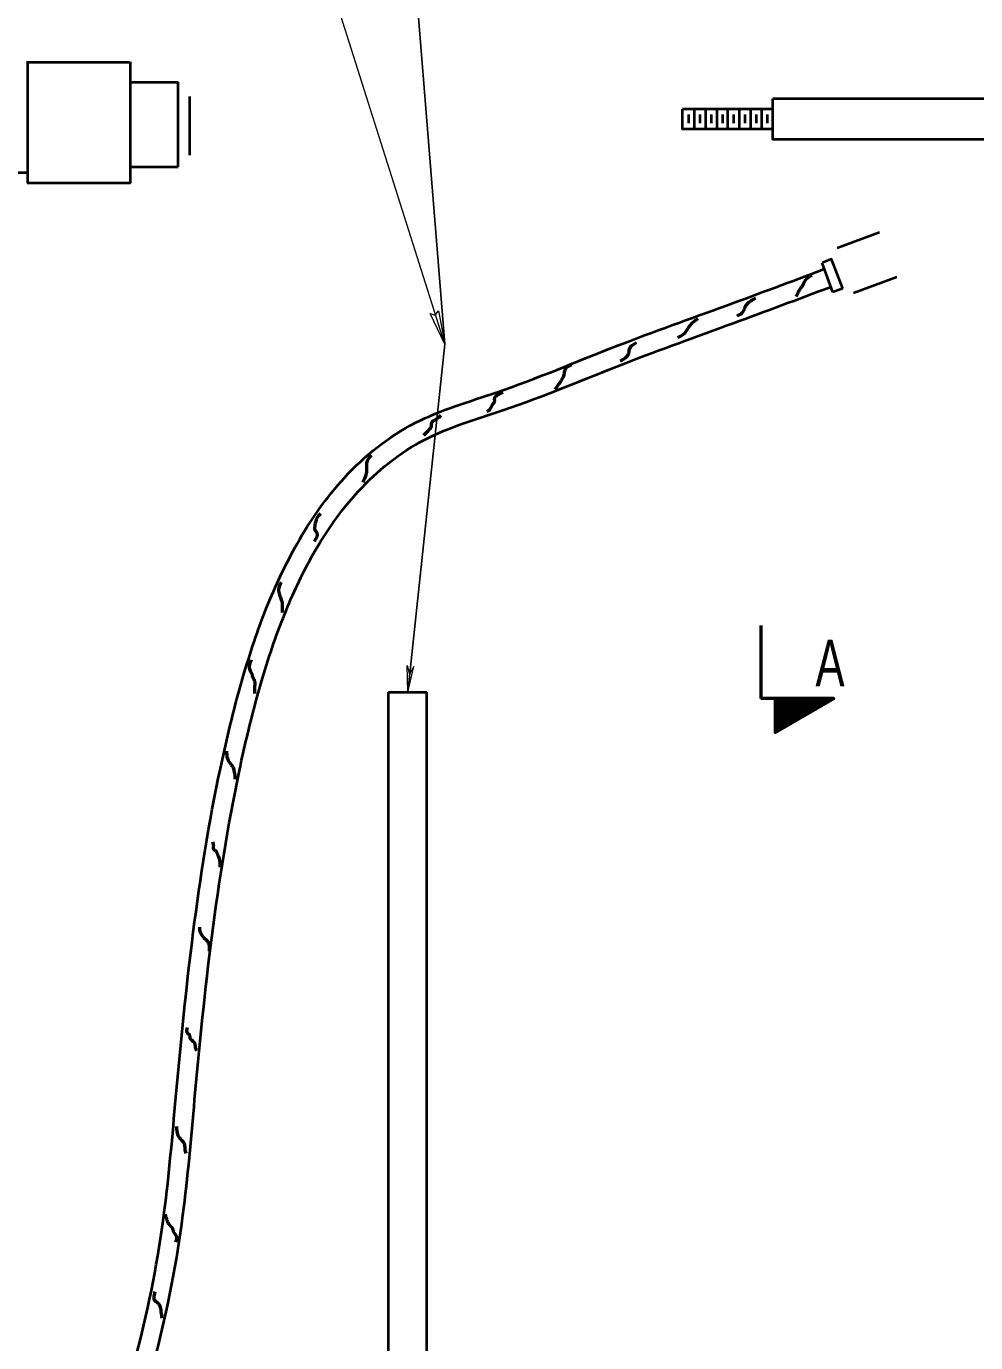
# Model space of a CAD drawing. Extents: x 312583 to 312854, y 144419 to 144597.
# Drawn here: x 312750.38 to 312765.92, y 144447.26 to 144468.81 of the extents above; entities that cross this region are included whole.
import ezdxf
from ezdxf.enums import TextEntityAlignment as Align

# ---------------------------------------------------------------- set-up
doc = ezdxf.new("R2010")
doc.units = 0
doc.header["$LTSCALE"] = 0.3
doc.layers.add('1', color=7, linetype='Continuous', lineweight=13)
doc.layers.add('2', color=7, linetype='Continuous', lineweight=13)

msp = doc.modelspace()

# ---------------------------------------------------------------- linework, layer by layer
at = {"layer": '1', "lineweight": 40}
for p, q in [((312752.069, 144468.2244), (312750.3824, 144468.2244)), ((312750.4054, 144466.2464), (312750.4054, 144468.2168)), ((312752.0844, 144466.2464), (312752.0844, 144468.2321)), ((312752.0844, 144467.9024), (312752.8664, 144467.9024)), ((312752.8664, 144466.5148), (312752.8664, 144467.9024)), ((312753.058, 144466.7064), (312753.058, 144467.6648)), ((312767.0037, 144467.6264), (312762.603, 144467.6264)), ((312762.603, 144467.4578), (312761.1234, 144467.4578)), ((312761.223, 144467.3734), (312761.223, 144467.2278)), ((312761.315, 144467.4578), (312761.315, 144467.1281)), ((312761.407, 144467.3734), (312761.407, 144467.2278)), ((312761.499, 144467.4578), (312761.499, 144467.1281)), ((312761.591, 144467.3734), (312761.591, 144467.2278)), ((312761.683, 144467.4578), (312761.683, 144467.1281)), ((312761.775, 144467.3734), (312761.775, 144467.2278)), ((312761.867, 144467.1281), (312761.867, 144467.4578)), ((312761.959, 144467.3734), (312761.959, 144467.2278)), ((312762.051, 144467.4578), (312762.051, 144467.1281)), ((312762.143, 144467.3734), (312762.143, 144467.2278)), ((312762.235, 144467.4578), (312762.235, 144467.1281)), ((312762.327, 144467.3734), (312762.327, 144467.2278)), ((312762.419, 144467.4578), (312762.419, 144467.1281)), ((312762.511, 144467.3734), (312762.511, 144467.2278)), ((312752.092, 144466.5148), (312752.8664, 144466.5148)), ((312750.045, 144466.4228), (312750.4054, 144466.4228)), ((312752.0844, 144466.2464), (312750.39, 144466.2464)), ((312764.351, 144465.4414), (312763.6534, 144465.1808)), ((312763.5844, 144464.4601), (312763.408, 144464.9431)), ((312764.6347, 144464.7054), (312763.9217, 144464.4448)), ((312763.7454, 144464.5214), (312763.5844, 144464.4601)), ((312756.3087, 144457.9128), (312756.9374, 144457.9128)), ((312756.3087, 144445.6231), (312756.3087, 144457.9128)), ((312756.9374, 144445.6231), (312756.9374, 144457.9128))]:
    msp.add_line(p, q, dxfattribs=at)
at = {"layer": '1', "lineweight": 53}
for p in [(312762.4037, 144459.0014), (312762.6414, 144457.8054)]:
    msp.add_line(p, (312762.4037, 144457.8054), dxfattribs=at)
at = {"layer": '1', "lineweight": 35}
for p, q in [((312762.6414, 144457.7978), (312762.879, 144457.3914)), ((312762.6414, 144457.7671), (312762.8637, 144457.3838)), ((312762.6414, 144457.7518), (312762.856, 144457.3761)), ((312762.6414, 144457.7211), (312762.8407, 144457.3761)), ((312762.6414, 144457.6981), (312762.833, 144457.3684)), ((312762.6414, 144457.6751), (312762.8254, 144457.3608)), ((312762.6414, 144457.6521), (312762.81, 144457.3531)), ((312762.6414, 144457.6291), (312762.8024, 144457.3454)), ((312762.649, 144457.8054), (312762.8867, 144457.3991)), ((312762.6644, 144457.8054), (312762.8944, 144457.3991)), ((312762.6797, 144457.8054), (312762.9097, 144457.4068)), ((312762.6874, 144457.8054), (312762.9174, 144457.4144)), ((312762.7027, 144457.8054), (312762.925, 144457.4221)), ((312762.718, 144457.8054), (312762.9404, 144457.4221)), ((312762.7334, 144457.8054), (312762.948, 144457.4298)), ((312762.741, 144457.8054), (312762.9557, 144457.4374)), ((312762.7564, 144457.8054), (312762.971, 144457.4451)), ((312762.7717, 144457.8054), (312762.9787, 144457.4528)), ((312762.787, 144457.8054), (312762.9864, 144457.4528)), ((312762.8024, 144457.8054), (312763.0017, 144457.4604)), ((312762.8177, 144457.8054), (312763.0094, 144457.4681)), ((312762.8254, 144457.8054), (312763.017, 144457.4758)), ((312762.8407, 144457.8054), (312763.0324, 144457.4834)), ((312762.856, 144457.8054), (312763.04, 144457.4834)), ((312762.8714, 144457.8054), (312763.0477, 144457.4911)), ((312762.879, 144457.8054), (312763.063, 144457.4988)), ((312762.8944, 144457.8054), (312763.0707, 144457.5064)), ((312762.9097, 144457.8054), (312763.0784, 144457.5064)), ((312762.925, 144457.8054), (312763.0937, 144457.5141)), ((312762.9404, 144457.8054), (312763.1014, 144457.5218)), ((312762.9557, 144457.8054), (312763.109, 144457.5294)), ((312762.9634, 144457.8054), (312763.1244, 144457.5294)), ((312762.9787, 144457.8054), (312763.132, 144457.5371)), ((312762.994, 144457.8054), (312763.1474, 144457.5448)), ((312763.0094, 144457.8054), (312763.155, 144457.5524)), ((312763.0247, 144457.8054), (312763.1627, 144457.5601)), ((312763.0324, 144457.8054), (312763.178, 144457.5601)), ((312763.0477, 144457.8054), (312763.1857, 144457.5678)), ((312763.063, 144457.8054), (312763.1934, 144457.5754)), ((312763.0784, 144457.8054), (312763.2087, 144457.5831)), ((312763.0937, 144457.8054), (312763.2164, 144457.5831)), ((312763.109, 144457.8054), (312763.224, 144457.5908)), ((312763.1167, 144457.8054), (312763.2394, 144457.5984)), ((312763.132, 144457.8054), (312763.247, 144457.6061)), ((312763.1474, 144457.8054), (312763.2624, 144457.6061)), ((312763.1627, 144457.8054), (312763.27, 144457.6138)), ((312763.178, 144457.8054), (312763.2777, 144457.6214)), ((312763.1857, 144457.8054), (312763.293, 144457.6291)), ((312763.201, 144457.8054), (312763.3007, 144457.6368)), ((312763.2164, 144457.8054), (312763.3084, 144457.6444)), ((312763.2317, 144457.8054), (312763.3237, 144457.6444)), ((312763.2394, 144457.8054), (312763.3314, 144457.6521)), ((312763.2547, 144457.8054), (312763.339, 144457.6598)), ((312763.27, 144457.8054), (312763.3544, 144457.6674)), ((312763.2854, 144457.8054), (312763.362, 144457.6674)), ((312763.3007, 144457.8054), (312763.3774, 144457.6751)), ((312763.3084, 144457.8054), (312763.385, 144457.6828)), ((312763.3237, 144457.8054), (312763.3927, 144457.6904)), ((312763.339, 144457.8054), (312763.408, 144457.6904)), ((312763.3544, 144457.8054), (312763.4157, 144457.6981)), ((312763.3697, 144457.8054), (312763.4234, 144457.7058)), ((312763.3774, 144457.8054), (312763.4387, 144457.7134)), ((312763.3927, 144457.8054), (312763.4464, 144457.7211)), ((312763.408, 144457.8054), (312763.454, 144457.7211)), ((312763.4234, 144457.8054), (312763.4694, 144457.7288)), ((312763.4387, 144457.8054), (312763.477, 144457.7364)), ((312763.454, 144457.8054), (312763.4847, 144457.7441)), ((312763.4617, 144457.8054), (312763.5, 144457.7518)), ((312763.477, 144457.8054), (312763.5077, 144457.7518)), ((312763.4924, 144457.8054), (312763.5154, 144457.7594)), ((312763.5077, 144457.8054), (312763.5307, 144457.7671)), ((312763.523, 144457.8054), (312763.5384, 144457.7748)), ((312763.5307, 144457.8054), (312763.546, 144457.7748)), ((312763.546, 144457.8054), (312763.5614, 144457.7824)), ((312763.5614, 144457.8054), (312763.569, 144457.7901)), ((312763.5767, 144457.8054), (312763.5767, 144457.7978)), ((312763.592, 144457.8054), (312763.592, 144457.7978)), ((312762.6414, 144457.6061), (312762.7947, 144457.3378)), ((312762.6414, 144457.5831), (312762.7794, 144457.3378)), ((312762.6414, 144457.5524), (312762.7717, 144457.3301)), ((312762.6414, 144457.5294), (312762.764, 144457.3224)), ((312762.6414, 144457.5064), (312762.7487, 144457.3148)), ((312762.6414, 144457.4834), (312762.741, 144457.3148)), ((312762.6414, 144457.4604), (312762.7257, 144457.3071)), ((312762.6414, 144457.4374), (312762.718, 144457.2994)), ((312762.6414, 144457.4144), (312762.7104, 144457.2918)), ((312762.6414, 144457.3838), (312762.695, 144457.2918)), ((312762.6414, 144457.3684), (312762.6874, 144457.2841)), ((312762.6414, 144457.3378), (312762.6797, 144457.2764)), ((312762.6414, 144457.3148), (312762.6644, 144457.2688)), ((312762.6414, 144457.2918), (312762.6567, 144457.2611)), ((312762.6414, 144457.2688), (312762.649, 144457.2611))]:
    msp.add_line(p, q, dxfattribs=at)
at = {"layer": '1'}
msp.add_lwpolyline([(312757.2287, 144463.6091), (312753.6484, 144474.9174), (312751.793, 144474.9174)], dxfattribs=at)
at = {"layer": '1', "lineweight": 40}
for points in [[(312767.0037, 144466.9594), (312762.603, 144466.9594), (312762.603, 144467.6264)], [(312762.603, 144467.1281), (312761.1234, 144467.1281), (312761.1234, 144467.4578)], [(312763.7454, 144464.5214), (312763.5614, 144465.0044), (312763.408, 144464.9431)]]:
    msp.add_lwpolyline(points, dxfattribs=at)
at = {"layer": '1'}
msp.add_lwpolyline([(312757.129, 144464.1534), (312757.2287, 144463.6091), (312756.991, 144464.1151), (312757.0754, 144464.0844)], close=True, dxfattribs=at)
at = {"layer": '1', "lineweight": 53}
msp.add_lwpolyline([(312762.6414, 144457.8054), (312762.6414, 144457.2534), (312763.5997, 144457.8054)], close=True, dxfattribs=at)
at = {"layer": '1', "lineweight": 40}
for points in [[(312744.5787, 144450.6524), (312744.617, 144448.6208), (312744.6707, 144446.7501), (312744.939, 144444.6341), (312745.468, 144443.1238), (312746.2194, 144442.3111), (312747.4077, 144441.9814), (312748.3354, 144442.0888), (312749.5314, 144442.6561), (312750.574, 144443.6144), (312751.5324, 144445.2091), (312752.1994, 144447.1334), (312752.6364, 144449.3951), (312752.828, 144451.2811), (312753.5564, 144456.6631), (312753.9474, 144458.2271), (312754.346, 144459.3771), (312754.8137, 144460.3431), (312755.588, 144461.4241), (312756.7457, 144462.3211), (312758.072, 144462.8194), (312760.0577, 144463.5861), (312761.844, 144464.2454), (312763.431, 144464.8358)], [(312744.2644, 144450.6448), (312744.3027, 144448.6131), (312744.3564, 144446.7271), (312744.6324, 144444.5651), (312745.1997, 144442.9551), (312746.0507, 144442.0351), (312747.3847, 144441.6671), (312748.4274, 144441.7898), (312749.7077, 144442.3954), (312750.8117, 144443.4151), (312751.816, 144445.0788), (312752.4984, 144447.0568), (312752.943, 144449.3491), (312753.1347, 144451.2428), (312753.863, 144456.6018), (312754.2464, 144458.1428), (312754.6374, 144459.2621), (312755.082, 144460.1821), (312755.818, 144461.2018), (312756.899, 144462.0451), (312758.1794, 144462.5281), (312760.1727, 144463.2948), (312761.9514, 144463.9541), (312763.5384, 144464.5444)]]:
    msp.add_spline(points, degree=3, dxfattribs=at)
at = {"layer": '1', "lineweight": 53}
for points in [[(312763.2394, 144464.7361), (312763.1474, 144464.6748), (312763.086, 144464.5674), (312763.0477, 144464.5138), (312762.9864, 144464.3911)], [(312762.3194, 144464.3604), (312762.1737, 144464.2608), (312762.143, 144464.2148), (312762.1124, 144464.1381), (312762.0127, 144464.0691)], [(312761.3764, 144464.0231), (312761.246, 144463.9234), (312761.154, 144463.7854), (312761.039, 144463.7164)], [(312760.372, 144463.6321), (312760.2494, 144463.5248), (312760.234, 144463.4481), (312760.1037, 144463.3331)], [(312759.3064, 144463.2718), (312759.199, 144463.1951), (312759.1837, 144463.1338), (312759.1684, 144463.0724), (312759.1224, 144462.9958), (312759.0304, 144462.8654)], [(312758.1794, 144462.8194), (312758.0874, 144462.7734), (312758.0414, 144462.7121), (312758.0414, 144462.6661), (312758.0107, 144462.6201), (312757.9647, 144462.5358), (312757.9187, 144462.5051)], [(312757.1674, 144462.4438), (312757.0907, 144462.3824), (312757.0217, 144462.3364), (312757.0064, 144462.3058), (312757.0064, 144462.2598), (312756.9757, 144462.2138), (312756.8837, 144462.1141)], [(312756.025, 144461.7921), (312755.9484, 144461.6618), (312755.9484, 144461.5698), (312755.9484, 144461.5391), (312755.933, 144461.4471), (312755.887, 144461.3474)], [(312755.197, 144460.8338), (312755.1357, 144460.7571), (312755.105, 144460.6498), (312755.105, 144460.5654), (312755.1357, 144460.5194), (312755.0897, 144460.3814)], [(312754.553, 144459.7068), (312754.507, 144459.5918), (312754.5224, 144459.5074), (312754.5454, 144459.4461), (312754.5684, 144459.3771), (312754.5684, 144459.3004), (312754.5684, 144459.2161)], [(312754.0624, 144458.4418), (312754.0317, 144458.3574), (312754.0317, 144458.2961), (312754.0624, 144458.2271), (312754.0854, 144458.1581), (312754.116, 144458.0891), (312754.116, 144458.0124), (312754.116, 144457.8898)], [(312753.656, 144456.9468), (312753.6714, 144456.8241), (312753.725, 144456.7321), (312753.7557, 144456.6938), (312753.7787, 144456.6248), (312753.794, 144456.5328), (312753.794, 144456.4868)], [(312753.426, 144455.4594), (312753.4414, 144455.3981), (312753.4414, 144455.3444), (312753.4797, 144455.3138), (312753.5027, 144455.2754), (312753.5104, 144455.2524), (312753.5257, 144455.2141), (312753.5487, 144455.0991), (312753.5487, 144455.0454)], [(312753.2114, 144454.0641), (312753.2267, 144453.9798), (312753.265, 144453.9184), (312753.2957, 144453.8801), (312753.3494, 144453.8264), (312753.3647, 144453.7881), (312753.3724, 144453.6731)], [(312753.012, 144452.4234), (312753.0197, 144452.3238), (312753.0427, 144452.3084), (312753.058, 144452.2471), (312753.1117, 144452.1934), (312753.1347, 144452.1628), (312753.15, 144452.0708), (312753.173, 144452.0478)], [(312752.8357, 144450.7981), (312752.8587, 144450.6601), (312752.92, 144450.5758), (312752.9584, 144450.5298), (312752.9737, 144450.4301), (312752.989, 144450.3611)], [(312752.6517, 144449.3644), (312752.6824, 144449.2648), (312752.7054, 144449.2111), (312752.7744, 144449.1268), (312752.7897, 144449.0808), (312752.8357, 144448.9964), (312752.8204, 144448.9044)], [(312752.483, 144448.0918), (312752.4677, 144448.0228), (312752.4677, 144447.9691), (312752.5137, 144447.9231), (312752.552, 144447.8848), (312752.5827, 144447.7621), (312752.598, 144447.6624)]]:
    msp.add_spline(points, degree=3, dxfattribs=at)
at = {"layer": '2', "lineweight": 25}
for p in [(312756.623, 144471.1991), (312756.623, 144457.9128)]:
    msp.add_line(p, (312757.2287, 144463.6091), dxfattribs=at)
at = {"layer": '2'}
for p, q in [((312756.6154, 144458.3498), (312756.6537, 144458.2041)), ((312756.623, 144457.9128), (312756.6154, 144458.3498)), ((312756.623, 144457.9128), (312756.7227, 144458.3344)), ((312756.7227, 144458.3344), (312756.6537, 144458.2041))]:
    msp.add_line(p, q, dxfattribs=at)

# ---------------------------------------------------------------- texts
at = {"layer": '1', "width": 0.7}
msp.add_text('A', height=0.7666, dxfattribs=at).set_placement((312763.5383, 144458.0048), align=Align.CENTER)

doc.saveas('drawing.dxf')
